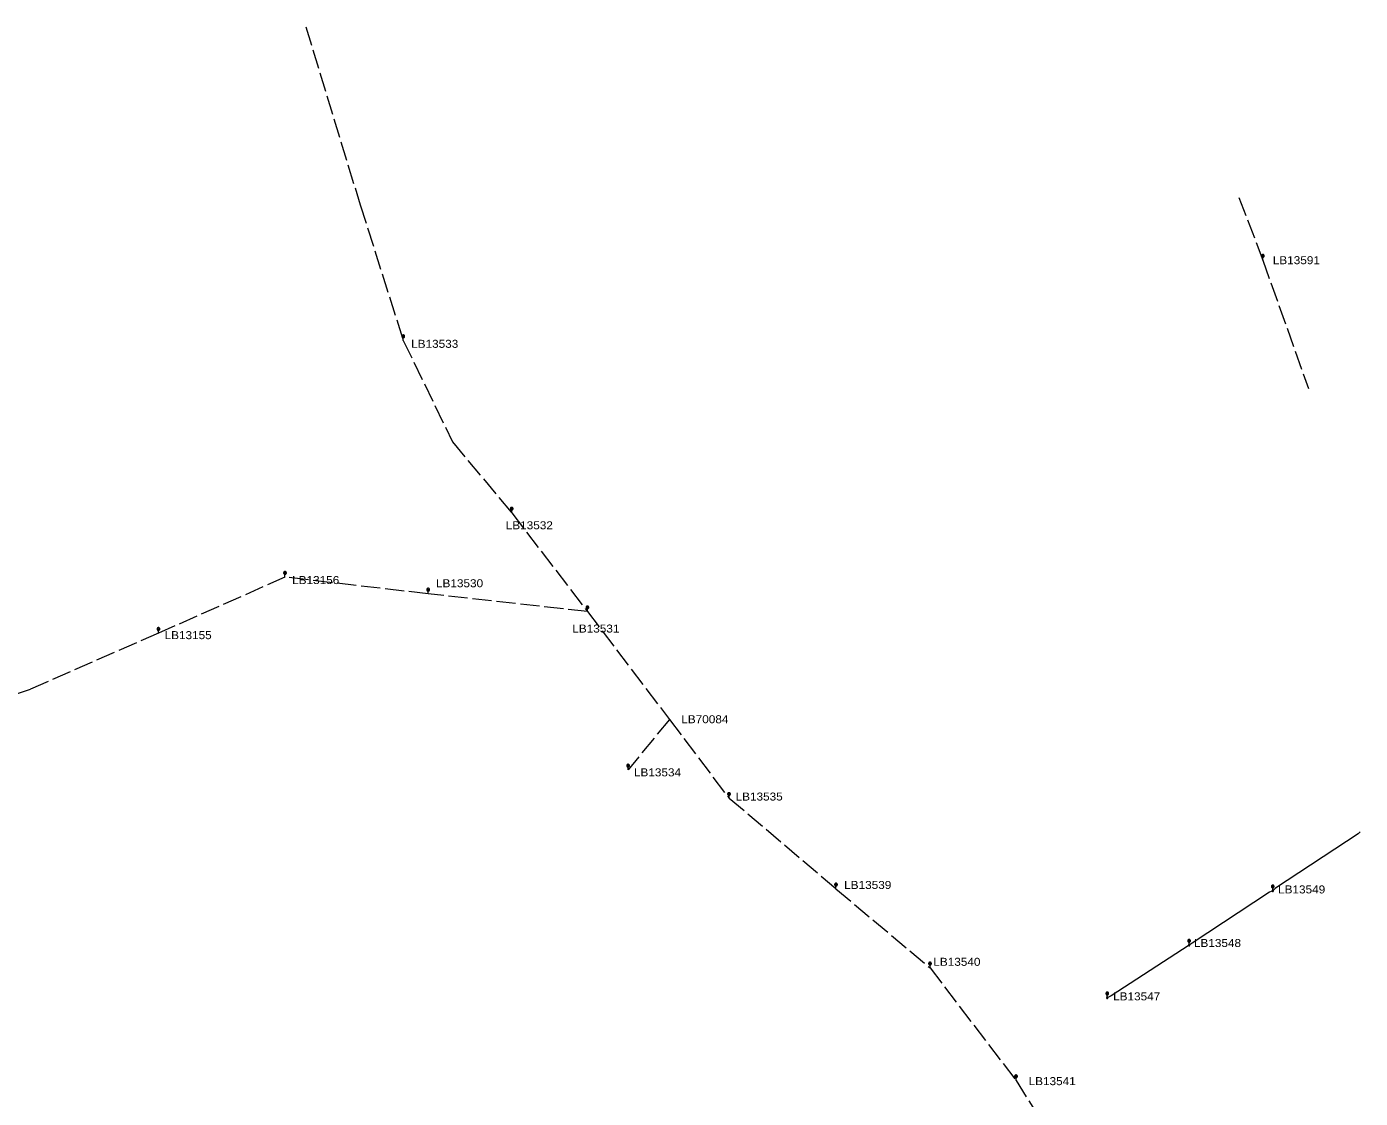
# Model space of a CAD drawing. Extents: x -691843 to -691118, y -976392 to -975793.
# Drawn here: x -691478.9 to -691117.8, y -976083.1 to -975792.9 of the extents above; entities that cross this region are included whole.
import ezdxf

# ---------------------------------------------------------------- set-up
doc = ezdxf.new("R2010")
doc.units = 0
doc.header["$LTSCALE"] = 0.87
doc.linetypes.add('LONG_DASHED', pattern=[7.5, 6, -1.5])
doc.layers.add('1', color=7, linetype='Continuous', lineweight=13)

msp = doc.modelspace()

# ---------------------------------------------------------------- linework, layer by layer
at = {"layer": '1', "linetype": 'LONG_DASHED'}
for p, q in [((-691150.726, -975839.114), (-691144.22, -975856.13)), ((-691144.22, -975856.13), (-691131.9, -975890.9)), ((-691304.88, -975980.46), (-691316.07, -975994.15)), ((-691259.78, -976026.35), (-691288.74, -976001.83)), ((-691259.78, -976026.35), (-691234.33, -976047.73))]:
    msp.add_line(p, q, dxfattribs=at)
at = {"layer": '1'}
for p, q in [((-691144.485, -975854.715), (-691143.955, -975855.245)), ((-691144.485, -975855.245), (-691143.955, -975854.715)), ((-691144.22, -975856.13), (-691144.22, -975855.355)), ((-691377.185, -975876.475), (-691376.655, -975877.005)), ((-691377.185, -975877.005), (-691376.655, -975876.475)), ((-691376.92, -975877.89), (-691376.92, -975877.115)), ((-691347.835, -975923.155), (-691347.305, -975923.685)), ((-691347.835, -975923.685), (-691347.305, -975923.155)), ((-691347.57, -975924.57), (-691347.57, -975923.795)), ((-691409.205, -975940.535), (-691408.675, -975941.065)), ((-691409.205, -975941.065), (-691408.675, -975940.535)), ((-691408.94, -975941.95), (-691408.94, -975941.175)), ((-691370.455, -975945.075), (-691369.925, -975945.605)), ((-691370.455, -975945.605), (-691369.925, -975945.075)), ((-691370.19, -975946.49), (-691370.19, -975945.715)), ((-691327.335, -975949.875), (-691326.805, -975950.405)), ((-691327.335, -975950.405), (-691326.805, -975949.875)), ((-691327.07, -975951.29), (-691327.07, -975950.515)), ((-691443.465, -975955.725), (-691442.935, -975956.255)), ((-691443.465, -975956.255), (-691442.935, -975955.725)), ((-691443.2, -975957.14), (-691443.2, -975956.365)), ((-691316.335, -975992.735), (-691315.805, -975993.265)), ((-691316.335, -975993.265), (-691315.805, -975992.735)), ((-691316.07, -975994.15), (-691316.07, -975993.375)), ((-691289.005, -976000.415), (-691288.475, -976000.945)), ((-691289.005, -976000.945), (-691288.475, -976000.415)), ((-691288.74, -976001.83), (-691288.74, -976001.055)), ((-691260.045, -976024.935), (-691259.515, -976025.465)), ((-691260.045, -976025.465), (-691259.515, -976024.935)), ((-691259.78, -976026.35), (-691259.78, -976025.575)), ((-691141.805, -976025.457), (-691141.275, -976025.987)), ((-691141.805, -976025.987), (-691141.275, -976025.457)), ((-691141.54, -976026.872), (-691141.54, -976026.097)), ((-691164.464, -976040.169), (-691163.934, -976040.699)), ((-691164.464, -976040.699), (-691163.934, -976040.169)), ((-691164.199, -976041.584), (-691164.199, -976040.809)), ((-691234.595, -976046.315), (-691234.065, -976046.845)), ((-691234.595, -976046.845), (-691234.065, -976046.315)), ((-691234.33, -976047.73), (-691234.33, -976046.955)), ((-691186.606, -976054.429), (-691186.076, -976054.959)), ((-691186.606, -976054.959), (-691186.076, -976054.429)), ((-691211.315, -976076.855), (-691210.785, -976077.385)), ((-691211.315, -976077.385), (-691210.785, -976076.855)), ((-691211.05, -976078.27), (-691211.05, -976077.495))]:
    msp.add_line(p, q, dxfattribs=at)
at = {"layer": '1', "linetype": 'LONG_DASHED'}
for points in [[(-691403.33, -975792.9), (-691388.58, -975841.16), (-691376.92, -975877.89)], [(-691376.92, -975877.89), (-691363.58, -975905.33), (-691347.57, -975924.57), (-691327.07, -975951.29), (-691370.19, -975946.49)], [(-691370.19, -975946.49), (-691408.94, -975941.95), (-691443.2, -975957.14)], [(-691327.07, -975951.29), (-691304.88, -975980.46), (-691288.74, -976001.83)], [(-691443.2, -975957.14), (-691477.89, -975972.34), (-691515.41, -975985.24), (-691555.35, -975999.08), (-691590.61, -976010.79)], [(-691234.33, -976047.73), (-691211.05, -976078.27), (-691190.51, -976110.88)]]:
    msp.add_lwpolyline(points, dxfattribs=at)
at = {"layer": '1'}
for points in [[(-691143.845, -975854.98), (-691143.851, -975854.915), (-691143.868, -975854.852), (-691143.895, -975854.793), (-691143.933, -975854.739), (-691143.979, -975854.693), (-691144.032, -975854.655), (-691144.092, -975854.628), (-691144.155, -975854.611), (-691144.22, -975854.605), (-691144.285, -975854.611), (-691144.348, -975854.628), (-691144.408, -975854.655), (-691144.461, -975854.693), (-691144.507, -975854.739), (-691144.545, -975854.793), (-691144.572, -975854.852), (-691144.589, -975854.915), (-691144.595, -975854.98), (-691144.589, -975855.045), (-691144.572, -975855.108), (-691144.545, -975855.168), (-691144.507, -975855.221), (-691144.461, -975855.267), (-691144.408, -975855.305), (-691144.348, -975855.332), (-691144.285, -975855.349), (-691144.22, -975855.355), (-691144.155, -975855.349), (-691144.092, -975855.332), (-691144.032, -975855.305), (-691143.979, -975855.267), (-691143.933, -975855.221), (-691143.895, -975855.168), (-691143.868, -975855.108), (-691143.851, -975855.045)], [(-691376.545, -975876.74), (-691376.551, -975876.675), (-691376.568, -975876.612), (-691376.595, -975876.552), (-691376.633, -975876.499), (-691376.679, -975876.453), (-691376.732, -975876.415), (-691376.792, -975876.388), (-691376.855, -975876.371), (-691376.92, -975876.365), (-691376.985, -975876.371), (-691377.048, -975876.388), (-691377.108, -975876.415), (-691377.161, -975876.453), (-691377.207, -975876.499), (-691377.245, -975876.552), (-691377.272, -975876.612), (-691377.289, -975876.675), (-691377.295, -975876.74), (-691377.289, -975876.805), (-691377.272, -975876.868), (-691377.245, -975876.928), (-691377.207, -975876.981), (-691377.161, -975877.027), (-691377.108, -975877.065), (-691377.048, -975877.092), (-691376.985, -975877.109), (-691376.92, -975877.115), (-691376.855, -975877.109), (-691376.792, -975877.092), (-691376.732, -975877.065), (-691376.679, -975877.027), (-691376.633, -975876.981), (-691376.595, -975876.928), (-691376.568, -975876.868), (-691376.551, -975876.805)], [(-691347.195, -975923.42), (-691347.201, -975923.355), (-691347.218, -975923.292), (-691347.245, -975923.232), (-691347.283, -975923.179), (-691347.329, -975923.133), (-691347.383, -975923.095), (-691347.442, -975923.068), (-691347.505, -975923.051), (-691347.57, -975923.045), (-691347.635, -975923.051), (-691347.698, -975923.068), (-691347.758, -975923.095), (-691347.811, -975923.133), (-691347.857, -975923.179), (-691347.895, -975923.232), (-691347.922, -975923.292), (-691347.939, -975923.355), (-691347.945, -975923.42), (-691347.939, -975923.485), (-691347.922, -975923.548), (-691347.895, -975923.607), (-691347.857, -975923.661), (-691347.811, -975923.707), (-691347.758, -975923.745), (-691347.698, -975923.772), (-691347.635, -975923.789), (-691347.57, -975923.795), (-691347.505, -975923.789), (-691347.442, -975923.772), (-691347.383, -975923.745), (-691347.329, -975923.707), (-691347.283, -975923.661), (-691347.245, -975923.607), (-691347.218, -975923.548), (-691347.201, -975923.485)], [(-691408.565, -975940.8), (-691408.571, -975940.735), (-691408.588, -975940.672), (-691408.615, -975940.612), (-691408.653, -975940.559), (-691408.699, -975940.513), (-691408.753, -975940.475), (-691408.812, -975940.448), (-691408.875, -975940.431), (-691408.94, -975940.425), (-691409.005, -975940.431), (-691409.068, -975940.448), (-691409.128, -975940.475), (-691409.181, -975940.513), (-691409.227, -975940.559), (-691409.265, -975940.612), (-691409.292, -975940.672), (-691409.309, -975940.735), (-691409.315, -975940.8), (-691409.309, -975940.865), (-691409.292, -975940.928), (-691409.265, -975940.987), (-691409.227, -975941.041), (-691409.181, -975941.087), (-691409.128, -975941.125), (-691409.068, -975941.152), (-691409.005, -975941.169), (-691408.94, -975941.175), (-691408.875, -975941.169), (-691408.812, -975941.152), (-691408.753, -975941.125), (-691408.699, -975941.087), (-691408.653, -975941.041), (-691408.615, -975940.987), (-691408.588, -975940.928), (-691408.571, -975940.865)], [(-691369.815, -975945.34), (-691369.821, -975945.275), (-691369.838, -975945.212), (-691369.865, -975945.153), (-691369.903, -975945.099), (-691369.949, -975945.053), (-691370.003, -975945.015), (-691370.062, -975944.988), (-691370.125, -975944.971), (-691370.19, -975944.965), (-691370.255, -975944.971), (-691370.318, -975944.988), (-691370.378, -975945.015), (-691370.431, -975945.053), (-691370.477, -975945.099), (-691370.515, -975945.153), (-691370.542, -975945.212), (-691370.559, -975945.275), (-691370.565, -975945.34), (-691370.559, -975945.405), (-691370.542, -975945.468), (-691370.515, -975945.528), (-691370.477, -975945.581), (-691370.431, -975945.627), (-691370.378, -975945.665), (-691370.318, -975945.692), (-691370.255, -975945.709), (-691370.19, -975945.715), (-691370.125, -975945.709), (-691370.062, -975945.692), (-691370.003, -975945.665), (-691369.949, -975945.627), (-691369.903, -975945.581), (-691369.865, -975945.528), (-691369.838, -975945.468), (-691369.821, -975945.405)], [(-691326.695, -975950.14), (-691326.701, -975950.075), (-691326.718, -975950.012), (-691326.745, -975949.952), (-691326.783, -975949.899), (-691326.829, -975949.853), (-691326.883, -975949.815), (-691326.942, -975949.788), (-691327.005, -975949.771), (-691327.07, -975949.765), (-691327.135, -975949.771), (-691327.198, -975949.788), (-691327.258, -975949.815), (-691327.311, -975949.853), (-691327.357, -975949.899), (-691327.395, -975949.952), (-691327.422, -975950.012), (-691327.439, -975950.075), (-691327.445, -975950.14), (-691327.439, -975950.205), (-691327.422, -975950.268), (-691327.395, -975950.328), (-691327.357, -975950.381), (-691327.311, -975950.427), (-691327.258, -975950.465), (-691327.198, -975950.492), (-691327.135, -975950.509), (-691327.07, -975950.515), (-691327.005, -975950.509), (-691326.942, -975950.492), (-691326.883, -975950.465), (-691326.829, -975950.427), (-691326.783, -975950.381), (-691326.745, -975950.328), (-691326.718, -975950.268), (-691326.701, -975950.205)], [(-691442.825, -975955.99), (-691442.831, -975955.925), (-691442.848, -975955.862), (-691442.875, -975955.802), (-691442.913, -975955.749), (-691442.959, -975955.703), (-691443.013, -975955.665), (-691443.072, -975955.638), (-691443.135, -975955.621), (-691443.2, -975955.615), (-691443.265, -975955.621), (-691443.328, -975955.638), (-691443.388, -975955.665), (-691443.441, -975955.703), (-691443.487, -975955.749), (-691443.525, -975955.802), (-691443.552, -975955.862), (-691443.569, -975955.925), (-691443.575, -975955.99), (-691443.569, -975956.055), (-691443.552, -975956.118), (-691443.525, -975956.178), (-691443.487, -975956.231), (-691443.441, -975956.277), (-691443.388, -975956.315), (-691443.328, -975956.342), (-691443.265, -975956.359), (-691443.2, -975956.365), (-691443.135, -975956.359), (-691443.072, -975956.342), (-691443.013, -975956.315), (-691442.959, -975956.277), (-691442.913, -975956.231), (-691442.875, -975956.178), (-691442.848, -975956.118), (-691442.831, -975956.055)], [(-691315.695, -975993), (-691315.701, -975992.935), (-691315.718, -975992.872), (-691315.745, -975992.812), (-691315.783, -975992.759), (-691315.829, -975992.713), (-691315.883, -975992.675), (-691315.942, -975992.648), (-691316.005, -975992.631), (-691316.07, -975992.625), (-691316.135, -975992.631), (-691316.198, -975992.648), (-691316.258, -975992.675), (-691316.311, -975992.713), (-691316.357, -975992.759), (-691316.395, -975992.812), (-691316.422, -975992.872), (-691316.439, -975992.935), (-691316.445, -975993), (-691316.439, -975993.065), (-691316.422, -975993.128), (-691316.395, -975993.188), (-691316.357, -975993.241), (-691316.311, -975993.287), (-691316.258, -975993.325), (-691316.198, -975993.352), (-691316.135, -975993.369), (-691316.07, -975993.375), (-691316.005, -975993.369), (-691315.942, -975993.352), (-691315.883, -975993.325), (-691315.829, -975993.287), (-691315.783, -975993.241), (-691315.745, -975993.188), (-691315.718, -975993.128), (-691315.701, -975993.065)], [(-691288.365, -976000.68), (-691288.371, -976000.615), (-691288.388, -976000.552), (-691288.415, -976000.492), (-691288.453, -976000.439), (-691288.499, -976000.393), (-691288.552, -976000.355), (-691288.612, -976000.328), (-691288.675, -976000.311), (-691288.74, -976000.305), (-691288.805, -976000.311), (-691288.868, -976000.328), (-691288.928, -976000.355), (-691288.981, -976000.393), (-691289.027, -976000.439), (-691289.065, -976000.492), (-691289.092, -976000.552), (-691289.109, -976000.615), (-691289.115, -976000.68), (-691289.109, -976000.745), (-691289.092, -976000.808), (-691289.065, -976000.867), (-691289.027, -976000.921), (-691288.981, -976000.967), (-691288.928, -976001.005), (-691288.868, -976001.032), (-691288.805, -976001.049), (-691288.74, -976001.055), (-691288.675, -976001.049), (-691288.612, -976001.032), (-691288.552, -976001.005), (-691288.499, -976000.967), (-691288.453, -976000.921), (-691288.415, -976000.867), (-691288.388, -976000.808), (-691288.371, -976000.745)], [(-691259.405, -976025.2), (-691259.411, -976025.135), (-691259.428, -976025.072), (-691259.455, -976025.013), (-691259.493, -976024.959), (-691259.539, -976024.913), (-691259.592, -976024.875), (-691259.652, -976024.848), (-691259.715, -976024.831), (-691259.78, -976024.825), (-691259.845, -976024.831), (-691259.908, -976024.848), (-691259.968, -976024.875), (-691260.021, -976024.913), (-691260.067, -976024.959), (-691260.105, -976025.013), (-691260.132, -976025.072), (-691260.149, -976025.135), (-691260.155, -976025.2), (-691260.149, -976025.265), (-691260.132, -976025.328), (-691260.105, -976025.388), (-691260.067, -976025.441), (-691260.021, -976025.487), (-691259.968, -976025.525), (-691259.908, -976025.552), (-691259.845, -976025.569), (-691259.78, -976025.575), (-691259.715, -976025.569), (-691259.652, -976025.552), (-691259.592, -976025.525), (-691259.539, -976025.487), (-691259.493, -976025.441), (-691259.455, -976025.388), (-691259.428, -976025.328), (-691259.411, -976025.265)], [(-691141.165, -976025.722), (-691141.171, -976025.657), (-691141.188, -976025.594), (-691141.215, -976025.535), (-691141.253, -976025.481), (-691141.299, -976025.435), (-691141.352, -976025.397), (-691141.412, -976025.37), (-691141.475, -976025.353), (-691141.54, -976025.347), (-691141.605, -976025.353), (-691141.668, -976025.37), (-691141.728, -976025.397), (-691141.781, -976025.435), (-691141.827, -976025.481), (-691141.865, -976025.535), (-691141.892, -976025.594), (-691141.909, -976025.657), (-691141.915, -976025.722), (-691141.909, -976025.787), (-691141.892, -976025.85), (-691141.865, -976025.91), (-691141.827, -976025.963), (-691141.781, -976026.009), (-691141.728, -976026.047), (-691141.668, -976026.074), (-691141.605, -976026.091), (-691141.54, -976026.097), (-691141.475, -976026.091), (-691141.412, -976026.074), (-691141.352, -976026.047), (-691141.299, -976026.009), (-691141.253, -976025.963), (-691141.215, -976025.91), (-691141.188, -976025.85), (-691141.171, -976025.787)], [(-691141.35, -976026.872), (-691141.353, -976026.839), (-691141.361, -976026.807), (-691141.375, -976026.777), (-691141.394, -976026.75), (-691141.418, -976026.726), (-691141.445, -976026.707), (-691141.475, -976026.693), (-691141.507, -976026.685), (-691141.54, -976026.682), (-691141.573, -976026.685), (-691141.605, -976026.693), (-691141.635, -976026.707), (-691141.662, -976026.726), (-691141.686, -976026.75), (-691141.705, -976026.777), (-691141.719, -976026.807), (-691141.727, -976026.839), (-691141.73, -976026.872), (-691141.727, -976026.905), (-691141.719, -976026.937), (-691141.705, -976026.967), (-691141.686, -976026.994), (-691141.662, -976027.018), (-691141.635, -976027.037), (-691141.605, -976027.051), (-691141.573, -976027.059), (-691141.54, -976027.062), (-691141.507, -976027.059), (-691141.475, -976027.051), (-691141.445, -976027.037), (-691141.418, -976027.018), (-691141.394, -976026.994), (-691141.375, -976026.967), (-691141.361, -976026.937), (-691141.353, -976026.905)], [(-691141.49, -976026.872), (-691141.491, -976026.863), (-691141.493, -976026.855), (-691141.497, -976026.847), (-691141.502, -976026.84), (-691141.508, -976026.834), (-691141.515, -976026.829), (-691141.523, -976026.825), (-691141.531, -976026.823), (-691141.54, -976026.822), (-691141.549, -976026.823), (-691141.557, -976026.825), (-691141.565, -976026.829), (-691141.572, -976026.834), (-691141.578, -976026.84), (-691141.583, -976026.847), (-691141.587, -976026.855), (-691141.589, -976026.863), (-691141.59, -976026.872), (-691141.589, -976026.881), (-691141.587, -976026.889), (-691141.583, -976026.897), (-691141.578, -976026.904), (-691141.572, -976026.91), (-691141.565, -976026.915), (-691141.557, -976026.919), (-691141.549, -976026.921), (-691141.54, -976026.922), (-691141.531, -976026.921), (-691141.523, -976026.919), (-691141.515, -976026.915), (-691141.508, -976026.91), (-691141.502, -976026.904), (-691141.497, -976026.897), (-691141.493, -976026.889), (-691141.491, -976026.881)], [(-691163.824, -976040.434), (-691163.83, -976040.369), (-691163.847, -976040.306), (-691163.874, -976040.246), (-691163.912, -976040.193), (-691163.958, -976040.147), (-691164.012, -976040.109), (-691164.071, -976040.082), (-691164.134, -976040.065), (-691164.199, -976040.059), (-691164.264, -976040.065), (-691164.327, -976040.082), (-691164.386, -976040.109), (-691164.44, -976040.147), (-691164.486, -976040.193), (-691164.524, -976040.246), (-691164.551, -976040.306), (-691164.568, -976040.369), (-691164.574, -976040.434), (-691164.568, -976040.499), (-691164.551, -976040.562), (-691164.524, -976040.622), (-691164.486, -976040.675), (-691164.44, -976040.721), (-691164.386, -976040.759), (-691164.327, -976040.786), (-691164.264, -976040.803), (-691164.199, -976040.809), (-691164.134, -976040.803), (-691164.071, -976040.786), (-691164.012, -976040.759), (-691163.958, -976040.721), (-691163.912, -976040.675), (-691163.874, -976040.622), (-691163.847, -976040.562), (-691163.83, -976040.499)], [(-691164.009, -976041.584), (-691164.012, -976041.551), (-691164.02, -976041.519), (-691164.034, -976041.489), (-691164.053, -976041.462), (-691164.077, -976041.438), (-691164.104, -976041.419), (-691164.134, -976041.405), (-691164.166, -976041.397), (-691164.199, -976041.394), (-691164.232, -976041.397), (-691164.264, -976041.405), (-691164.294, -976041.419), (-691164.321, -976041.438), (-691164.345, -976041.462), (-691164.364, -976041.489), (-691164.378, -976041.519), (-691164.386, -976041.551), (-691164.389, -976041.584), (-691164.386, -976041.617), (-691164.378, -976041.649), (-691164.364, -976041.679), (-691164.345, -976041.706), (-691164.321, -976041.73), (-691164.294, -976041.749), (-691164.264, -976041.763), (-691164.232, -976041.771), (-691164.199, -976041.774), (-691164.166, -976041.771), (-691164.134, -976041.763), (-691164.104, -976041.749), (-691164.077, -976041.73), (-691164.053, -976041.706), (-691164.034, -976041.679), (-691164.02, -976041.649), (-691164.012, -976041.617)], [(-691164.149, -976041.584), (-691164.15, -976041.575), (-691164.152, -976041.567), (-691164.156, -976041.559), (-691164.161, -976041.552), (-691164.167, -976041.546), (-691164.174, -976041.541), (-691164.182, -976041.537), (-691164.19, -976041.535), (-691164.199, -976041.534), (-691164.208, -976041.535), (-691164.216, -976041.537), (-691164.224, -976041.541), (-691164.231, -976041.546), (-691164.237, -976041.552), (-691164.242, -976041.559), (-691164.246, -976041.567), (-691164.248, -976041.575), (-691164.249, -976041.584), (-691164.248, -976041.593), (-691164.246, -976041.601), (-691164.242, -976041.609), (-691164.237, -976041.616), (-691164.231, -976041.622), (-691164.224, -976041.627), (-691164.216, -976041.631), (-691164.208, -976041.633), (-691164.199, -976041.634), (-691164.19, -976041.633), (-691164.182, -976041.631), (-691164.174, -976041.627), (-691164.167, -976041.622), (-691164.161, -976041.616), (-691164.156, -976041.609), (-691164.152, -976041.601), (-691164.15, -976041.593)], [(-691233.955, -976046.58), (-691233.961, -976046.515), (-691233.978, -976046.452), (-691234.005, -976046.393), (-691234.043, -976046.339), (-691234.089, -976046.293), (-691234.142, -976046.255), (-691234.202, -976046.228), (-691234.265, -976046.211), (-691234.33, -976046.205), (-691234.395, -976046.211), (-691234.458, -976046.228), (-691234.518, -976046.255), (-691234.571, -976046.293), (-691234.617, -976046.339), (-691234.655, -976046.393), (-691234.682, -976046.452), (-691234.699, -976046.515), (-691234.705, -976046.58), (-691234.699, -976046.645), (-691234.682, -976046.708), (-691234.655, -976046.768), (-691234.617, -976046.821), (-691234.571, -976046.867), (-691234.518, -976046.905), (-691234.458, -976046.932), (-691234.395, -976046.949), (-691234.33, -976046.955), (-691234.265, -976046.949), (-691234.202, -976046.932), (-691234.142, -976046.905), (-691234.089, -976046.867), (-691234.043, -976046.821), (-691234.005, -976046.768), (-691233.978, -976046.708), (-691233.961, -976046.645)], [(-691185.966, -976054.694), (-691185.972, -976054.629), (-691185.989, -976054.566), (-691186.016, -976054.507), (-691186.054, -976054.453), (-691186.1, -976054.407), (-691186.154, -976054.369), (-691186.213, -976054.342), (-691186.276, -976054.325), (-691186.341, -976054.319), (-691186.406, -976054.325), (-691186.469, -976054.342), (-691186.528, -976054.369), (-691186.582, -976054.407), (-691186.628, -976054.453), (-691186.666, -976054.507), (-691186.693, -976054.566), (-691186.71, -976054.629), (-691186.716, -976054.694), (-691186.71, -976054.759), (-691186.693, -976054.822), (-691186.666, -976054.882), (-691186.628, -976054.935), (-691186.582, -976054.981), (-691186.528, -976055.019), (-691186.469, -976055.046), (-691186.406, -976055.063), (-691186.341, -976055.069), (-691186.276, -976055.063), (-691186.213, -976055.046), (-691186.154, -976055.019), (-691186.1, -976054.981), (-691186.054, -976054.935), (-691186.016, -976054.882), (-691185.989, -976054.822), (-691185.972, -976054.759)], [(-691186.151, -976055.844), (-691186.154, -976055.811), (-691186.162, -976055.779), (-691186.176, -976055.749), (-691186.195, -976055.722), (-691186.219, -976055.698), (-691186.246, -976055.679), (-691186.276, -976055.665), (-691186.308, -976055.657), (-691186.341, -976055.654), (-691186.374, -976055.657), (-691186.406, -976055.665), (-691186.436, -976055.679), (-691186.463, -976055.698), (-691186.487, -976055.722), (-691186.506, -976055.749), (-691186.52, -976055.779), (-691186.528, -976055.811), (-691186.531, -976055.844), (-691186.528, -976055.877), (-691186.52, -976055.909), (-691186.506, -976055.939), (-691186.487, -976055.966), (-691186.463, -976055.99), (-691186.436, -976056.009), (-691186.406, -976056.023), (-691186.374, -976056.031), (-691186.341, -976056.034), (-691186.308, -976056.031), (-691186.276, -976056.023), (-691186.246, -976056.009), (-691186.219, -976055.99), (-691186.195, -976055.966), (-691186.176, -976055.939), (-691186.162, -976055.909), (-691186.154, -976055.877)], [(-691186.291, -976055.844), (-691186.292, -976055.835), (-691186.294, -976055.827), (-691186.298, -976055.819), (-691186.303, -976055.812), (-691186.309, -976055.806), (-691186.316, -976055.801), (-691186.324, -976055.797), (-691186.332, -976055.795), (-691186.341, -976055.794), (-691186.35, -976055.795), (-691186.358, -976055.797), (-691186.366, -976055.801), (-691186.373, -976055.806), (-691186.379, -976055.812), (-691186.384, -976055.819), (-691186.388, -976055.827), (-691186.39, -976055.835), (-691186.391, -976055.844), (-691186.39, -976055.853), (-691186.388, -976055.861), (-691186.384, -976055.869), (-691186.379, -976055.876), (-691186.373, -976055.882), (-691186.366, -976055.887), (-691186.358, -976055.891), (-691186.35, -976055.893), (-691186.341, -976055.894), (-691186.332, -976055.893), (-691186.324, -976055.891), (-691186.316, -976055.887), (-691186.309, -976055.882), (-691186.303, -976055.876), (-691186.298, -976055.869), (-691186.294, -976055.861), (-691186.292, -976055.853)], [(-691210.675, -976077.12), (-691210.681, -976077.055), (-691210.698, -976076.992), (-691210.725, -976076.932), (-691210.763, -976076.879), (-691210.809, -976076.833), (-691210.862, -976076.795), (-691210.922, -976076.768), (-691210.985, -976076.751), (-691211.05, -976076.745), (-691211.115, -976076.751), (-691211.178, -976076.768), (-691211.238, -976076.795), (-691211.291, -976076.833), (-691211.337, -976076.879), (-691211.375, -976076.932), (-691211.402, -976076.992), (-691211.419, -976077.055), (-691211.425, -976077.12), (-691211.419, -976077.185), (-691211.402, -976077.248), (-691211.375, -976077.308), (-691211.337, -976077.361), (-691211.291, -976077.407), (-691211.238, -976077.445), (-691211.178, -976077.472), (-691211.115, -976077.489), (-691211.05, -976077.495), (-691210.985, -976077.489), (-691210.922, -976077.472), (-691210.862, -976077.445), (-691210.809, -976077.407), (-691210.763, -976077.361), (-691210.725, -976077.308), (-691210.698, -976077.248), (-691210.681, -976077.185)]]:
    msp.add_lwpolyline(points, close=True, dxfattribs=at)
for points in [[(-691117.839, -976010.905), (-691118.456, -976011.496), (-691140.769, -976026.183), (-691141.54, -976026.872)], [(-691141.54, -976026.872), (-691142.404, -976027.281), (-691163.337, -976041.016), (-691164.199, -976041.584)], [(-691164.199, -976041.584), (-691165.995, -976042.75), (-691185.323, -976055.308), (-691186.341, -976055.844), (-691186.341, -976055.069)]]:
    msp.add_lwpolyline(points, dxfattribs=at)

# ---------------------------------------------------------------- texts
at = {"layer": '1', "width": 1.1}
for s, height, p in [('LB13591', 2.167, (-691141.536, -975857.217)), ('LB13533', 2.167, (-691374.791, -975879.86)), ('LB13532', 2.167, (-691349.178, -975928.992)), ('LB13156', 2.167, (-691407.009, -975943.827)), ('LB13530', 2.167, (-691368.068, -975944.691)), ('LB13531', 2.167, (-691331.167, -975956.956)), ('LB13155', 2.167, (-691441.543, -975958.743)), ('LB70084', 2.168, (-691301.667, -975981.513)), ('LB13534', 2.167, (-691314.486, -975995.893)), ('LB13535', 2.167, (-691286.963, -976002.446)), ('LB13539', 2.167, (-691257.564, -976026.381)), ('LB13549', 2.167, (-691140.108, -976027.589)), ('LB13548', 2.167, (-691162.891, -976042.098)), ('LB13540', 2.167, (-691233.434, -976047.19)), ('LB13547', 2.167, (-691184.764, -976056.55)), ('LB13541', 2.167, (-691207.641, -976079.505))]:
    msp.add_text(s, height=height, dxfattribs=at).set_placement(p)

doc.saveas('drawing.dxf')
